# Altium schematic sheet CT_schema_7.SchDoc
size 287 x 160 mm
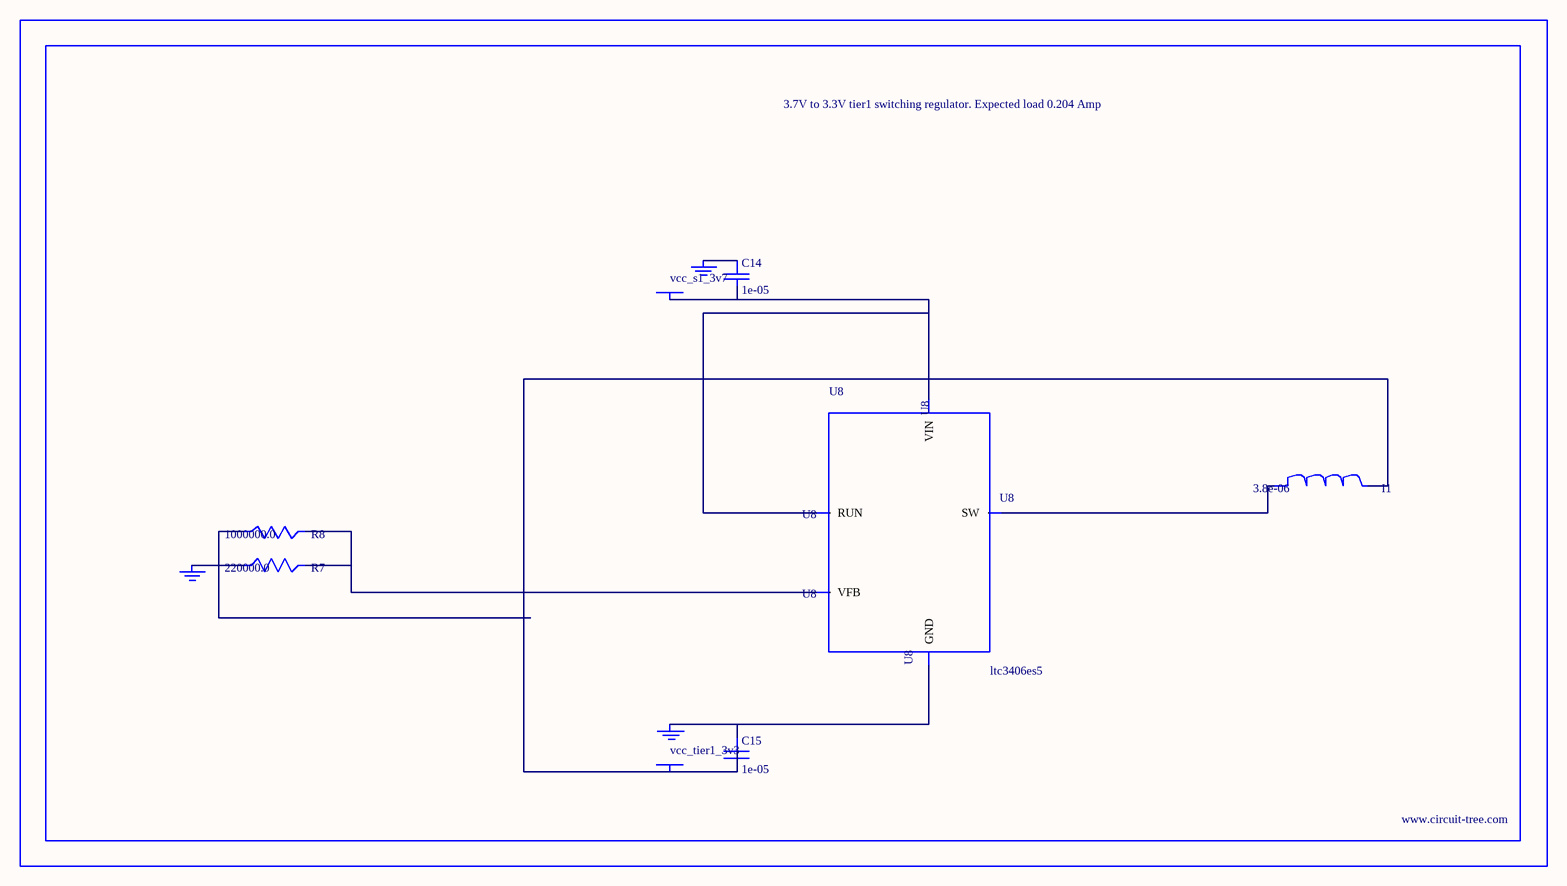
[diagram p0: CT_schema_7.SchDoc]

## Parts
BORDER6  (no value)
C14  1e-05  [C0805]
C15  1e-05  [C0805]
GND_INSTANCE_6_0  (no value)
GND_INSTANCE_6_1  (no value)
GND_INSTANCE_6_2  (no value)
I1  3.8e-06  [DR1040]
POWER_INSTANCE_6_0  vcc_tier1_3v3
POWER_INSTANCE_6_1  vcc_s1_3v7
R7  220000.0  [R0603]
R8  1000000.0  [R0603]
U8  ltc3406es5  [TSOT-23-5]

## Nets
NetC14_1: C14.1 GND_INSTANCE_6_1.0(GND)
NetC14_2: C14.2 POWER_INSTANCE_6_1.0(PWR) U8.1(RUN) U8.4(VIN)
NetC15_1: C15.1 GND_INSTANCE_6_0.0(GND) U8.2(GND)
NetC15_2: C15.2 I1.2 POWER_INSTANCE_6_0.0(PWR) R8.1
NetGND_INSTANCE_6_2_0: GND_INSTANCE_6_2.0(GND) R7.1
NetI1_1: I1.1 U8.3(SW)
NetR7_2: R7.2 R8.2 U8.5(VFB)

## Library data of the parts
BORDER6 = BORDER_PAGE6
C14 C15 = C0805C106K8RACTU
GND_INSTANCE_6_0-GND_INSTANCE_6_2 = GND
I1 = DR1040-3R8-R
POWER_INSTANCE_6_0 POWER_INSTANCE_6_1 = PWR
R7 = RC0603JR-07220KL
R8 = RC0603JR-071ML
